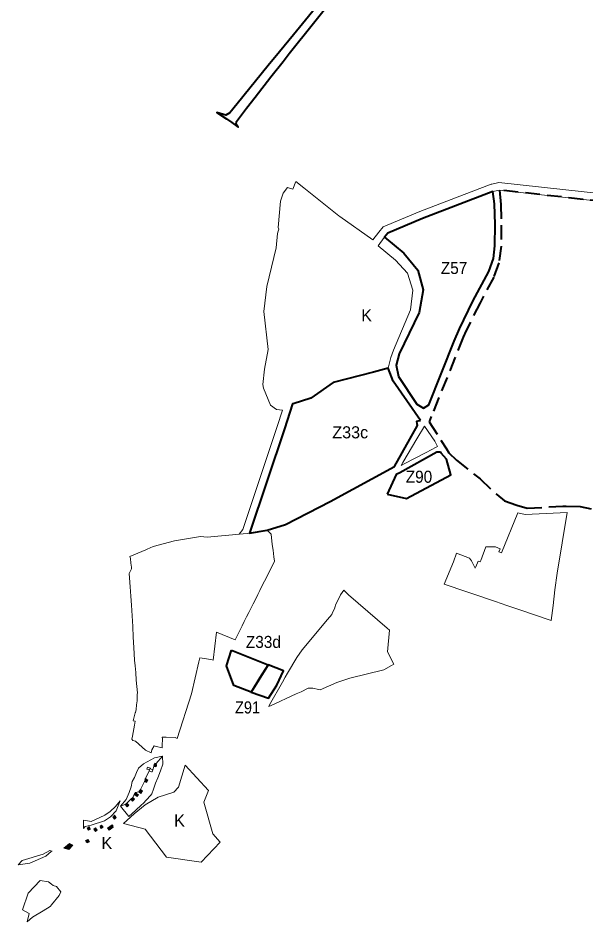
# Model space of a CAD drawing. Extents: x -650276 to -642489, y -1074425 to -1066658.
# Drawn here: x -648979 to -647851, y -1074425 to -1072629 of the extents above; entities that cross this region are included whole.
import ezdxf

# ---------------------------------------------------------------- set-up
doc = ezdxf.new("R2010")
doc.units = 0
doc.header["$LTSCALE"] = 9.6
doc.linetypes.add('MEDIUM_DASHED', pattern=[4.5, 3, -1.5])
for name, color, linetype, lineweight in [('1', 7, 'Continuous', 13), ('43', 7, 'Continuous', 13), ('44', 7, 'Continuous', 40), ('45', 7, 'Continuous', 40), ('46', 7, 'Continuous', 13), ('47', 7, 'Continuous', 13), ('61', 7, 'MEDIUM_DASHED', 40)]:
    doc.layers.add(name, color=color, linetype=linetype, lineweight=lineweight)

msp = doc.modelspace()

# ---------------------------------------------------------------- hatches: boundary and pattern name
at = {"layer": '1'}
for points in [[(-648706.9, -1074109.25), (-648704.01, -1074109.75), (-648704.38, -1074112.26), (-648703.29, -1074112.42), (-648703.74, -1074115.5), (-648704.71, -1074115.36), (-648704.9, -1074116.65), (-648708.61, -1074116.05), (-648707.91, -1074111.29), (-648707.22, -1074111.39)], [(-648727.44, -1074145.52), (-648725.66, -1074142.45), (-648726.64, -1074141.85), (-648725.61, -1074140.1), (-648723.09, -1074141.53), (-648720.64, -1074142.98), (-648723.51, -1074147.87)], [(-648731.11, -1074164.51), (-648734.73, -1074169.43), (-648738.83, -1074166.37), (-648735.22, -1074161.48)], [(-648751.18, -1074184.57), (-648747.5, -1074181.2), (-648750.88, -1074177.44), (-648754.61, -1074180.84)], [(-648739.31, -1074171.85), (-648742.22, -1074175.9), (-648748.17, -1074171.66), (-648745.37, -1074167.73), (-648743.97, -1074168.73), (-648743.97, -1074168.73)], [(-648761.71, -1074196.08), (-648758.47, -1074193.06), (-648762.43, -1074188.71), (-648765.67, -1074191.74)], [(-648787.14, -1074220.53), (-648783.43, -1074217.6), (-648784.21, -1074216.62), (-648787.24, -1074212.83), (-648788.26, -1074213.64), (-648787.58, -1074214.5), (-648790.3, -1074216.64)], [(-648834.62, -1074240.17), (-648835.22, -1074239.19), (-648837.67, -1074235.14), (-648838.8, -1074235.82), (-648838.27, -1074236.69), (-648841.13, -1074238.42), (-648838.64, -1074242.6)], [(-648821.27, -1074242.64), (-648824.7, -1074245.22), (-648828.21, -1074240.31), (-648824.82, -1074237.88)], [(-648813.64, -1074239.44), (-648809.8, -1074236.74), (-648812.71, -1074232.64), (-648815.51, -1074234.63), (-648814.75, -1074235.7), (-648815.76, -1074236.42)], [(-648800.8, -1074238.18), (-648791.75, -1074231.61), (-648789.51, -1074234.71), (-648790.46, -1074235.4), (-648789.81, -1074236.29), (-648797.83, -1074242.19)], [(-648844.44, -1074262.8), (-648839.91, -1074260.94), (-648839.51, -1074261.94), (-648838.46, -1074261.5), (-648836.72, -1074265.79), (-648841.46, -1074267.7), (-648842.1, -1074266.12), (-648842.92, -1074266.45), (-648843.1, -1074266.03), (-648843.33, -1074266.13), (-648843.55, -1074265.61), (-648843.31, -1074265.51)]]:
    msp.add_hatch(color=256, dxfattribs=at).paths.add_polyline_path(points)
at = {"layer": '47'}
msp.add_hatch(color=256, dxfattribs=at).paths.add_polyline_path([(-648876.21, -1074268.73), (-648887.619, -1074278.134), (-648877.799, -1074280.64), (-648870.041, -1074271.932)])

# ---------------------------------------------------------------- linework, layer by layer
at = {"layer": '1'}
for p, q in [((-648704.01, -1074109.75), (-648691.9, -1074095.66)), ((-648725.61, -1074140.1), (-648718.18, -1074124.67)), ((-648710.78, -1074122.56), (-648708.61, -1074116.05)), ((-648735.22, -1074161.48), (-648727.44, -1074145.52)), ((-648745.37, -1074167.73), (-648738.83, -1074166.37)), ((-648762.43, -1074188.71), (-648754.61, -1074180.84)), ((-648750.88, -1074177.44), (-648748.17, -1074171.66)), ((-648775.1, -1074194.97), (-648765.67, -1074191.74))]:
    msp.add_line(p, q, dxfattribs=at)
for points in [[(-648167.68, -1073492.02), (-648148.27, -1073481.86), (-648145.31, -1073480.31), (-648150.85, -1073469.67), (-648171.18, -1073440.16), (-648186.19, -1073465.35), (-648214.31, -1073512.51), (-648217.71, -1073518.22)], [(-648217.71, -1073518.22), (-648211.86, -1073515.16), (-648167.68, -1073492.02)], [(-647915.79, -1073796.07), (-647911.96, -1073765.02), (-647907.9, -1073732.08), (-647887.52, -1073611.77), (-647970.95, -1073615.21), (-647986.1, -1073612.18), (-648018, -1073691.73), (-648023.29, -1073689.72), (-648020.84, -1073683.33), (-648030.35, -1073679.74), (-648049.05, -1073679.67), (-648059.54, -1073706.72), (-648060.55, -1073709.31), (-648064.72, -1073707.89), (-648068.98, -1073719.26), (-648070.53, -1073722.09), (-648077.83, -1073707.36), (-648081.62, -1073702.08), (-648107.38, -1073692.13), (-648113.89, -1073709.39), (-648132.29, -1073753.96), (-648086.94, -1073768.97), (-648074.98, -1073772.93)], [(-648531.31, -1073654.08), (-648602.91, -1073660.32), (-648616.19, -1073659.15), (-648667.8, -1073668), (-648710.31, -1073679.13), (-648721.94, -1073684.11), (-648725.01, -1073685.42), (-648756.81, -1073699.03), (-648755.2, -1073703.08), (-648754.27, -1073711.87), (-648753.44, -1073719.78), (-648753.02, -1073723.7), (-648757.6, -1073732.5), (-648757, -1073741.26), (-648755.76, -1073759.24), (-648754.49, -1073777.63), (-648753.27, -1073795.38), (-648752.06, -1073816.42), (-648750.84, -1073837.88), (-648749.63, -1073859.01), (-648748.83, -1073879.38), (-648748.15, -1073892.33), (-648747.8, -1073896.44), (-648747.45, -1073900.56), (-648747.09, -1073904.68), (-648746.08, -1073916.36), (-648744.97, -1073929.3), (-648743.69, -1073944.2), (-648741.63, -1073969.96)], [(-648741.63, -1073969.96), (-648741.7, -1073972.86), (-648741.82, -1073977.79), (-648742, -1073985.49), (-648743.07, -1073993.69), (-648744.151, -1074002.577), (-648745.609, -1074008.621), (-648745.79, -1074009.12), (-648750.04, -1074025), (-648746.05, -1074026.17), (-648747.5, -1074033.74), (-648748.85, -1074041.09), (-648750.22, -1074048.45), (-648751.57, -1074055.82), (-648752.57, -1074061.85), (-648750.31, -1074064.07), (-648745.35, -1074065.36), (-648725.36, -1074083.48), (-648714.48, -1074088.54), (-648712.7, -1074083.01), (-648708.17, -1074075), (-648706.15, -1074075.52), (-648703.8, -1074076.13), (-648692.12, -1074079.16), (-648692.04, -1074071.48), (-648691.95, -1074063.59), (-648691.93, -1074061.16), (-648692.17, -1074057.75), (-648684.45, -1074057.86), (-648666.67, -1074058.64), (-648662.25, -1074060.63), (-648634.22, -1073971.89), (-648619.68, -1073908.23), (-648617.72, -1073900.06), (-648595.78, -1073903.41), (-648591.015, -1073904.525), (-648584.31, -1073849.37), (-648547.45, -1073864.3), (-648538.19, -1073845.84), (-648533.57, -1073836.64), (-648529.29, -1073828.1), (-648524.62, -1073818.8), (-648520.19, -1073809.96), (-648515.65, -1073800.92), (-648511.53, -1073792.7), (-648507.19, -1073784.05), (-648502.33, -1073774.36), (-648498.26, -1073766.24), (-648493.51, -1073756.79), (-648489.2, -1073748.19), (-648475.3, -1073720.49), (-648469.41, -1073707.95), (-648470.23, -1073699.85), (-648471.6, -1073686.38), (-648473.61, -1073674.84), (-648475.51, -1073654.52), (-648483.58, -1073646.7), (-648514.23, -1073652.37), (-648522.79, -1073653.23), (-648531.31, -1073654.08)], [(-648477.31, -1073995.35), (-648425.92, -1073971.61), (-648416.09, -1073967.48), (-648402.35, -1073960.34), (-648393.32, -1073960.33), (-648381.56, -1073963.36), (-648378.47, -1073963.46), (-648345.65, -1073948.97), (-648319.3, -1073940.41), (-648251.71, -1073923.92), (-648236.64, -1073915.49), (-648232.32, -1073912.96), (-648244.96, -1073888.56), (-648240.9, -1073844.99), (-648245.45, -1073841.08), (-648322.08, -1073775.04), (-648331.74, -1073765.85), (-648337.91, -1073774.87), (-648340.74, -1073780.66), (-648347.38, -1073793.82)], [(-648074.98, -1073772.93), (-648030.44, -1073788.51), (-648007.95, -1073796.14), (-647983.68, -1073804.37), (-647919.33, -1073826.21), (-647915.79, -1073796.07)], [(-648347.38, -1073793.82), (-648349.12, -1073800.06), (-648349.58, -1073801.08), (-648354.57, -1073812.08), (-648355.37, -1073813.85), (-648363.65, -1073823.85), (-648413.91, -1073884.54), (-648424.51, -1073899.37), (-648443.35, -1073930.53), (-648447.77, -1073938.64), (-648453.11, -1073948.16), (-648478.94, -1073993.79), (-648480.31, -1073996.63), (-648477.31, -1073995.35)], [(-648775.1, -1074194.97), (-648758.41, -1074215.05), (-648745.22, -1074203.28), (-648733.69, -1074192.38), (-648730.34, -1074189.22), (-648723.64, -1074182.09), (-648715.37, -1074173.28), (-648712.77, -1074170.51), (-648709.34, -1074161.26), (-648705.61, -1074149.4), (-648700.77, -1074138.18), (-648695.83, -1074124.88), (-648690.92, -1074111.64), (-648691.9, -1074095.66), (-648704.01, -1074109.75)], [(-648691.9, -1074095.66), (-648707.44, -1074098.79), (-648729.24, -1074110.84), (-648739.31, -1074119.01), (-648743.55, -1074127.69), (-648747.25, -1074137.56), (-648751.97, -1074146.03), (-648753.74, -1074156.28), (-648758.05, -1074167.41)], [(-648704.01, -1074109.75), (-648704.38, -1074112.26), (-648703.29, -1074112.42), (-648703.74, -1074115.5), (-648704.71, -1074115.36), (-648704.9, -1074116.65), (-648708.61, -1074116.05), (-648710.78, -1074122.56), (-648712.32, -1074126.72), (-648713.61, -1074126.32), (-648718.18, -1074124.67), (-648725.61, -1074140.1)], [(-648708.61, -1074116.05), (-648707.91, -1074111.29), (-648707.22, -1074111.39), (-648706.9, -1074109.25), (-648704.01, -1074109.75), (-648691.9, -1074095.66)], [(-648727.44, -1074145.52), (-648725.66, -1074142.45), (-648726.64, -1074141.85), (-648725.61, -1074140.1), (-648718.18, -1074124.67), (-648717.56, -1074122.89), (-648722.84, -1074120.98)], [(-648722.84, -1074120.98), (-648721.39, -1074116.99), (-648715.22, -1074119.43), (-648715.7, -1074120.74), (-648712.07, -1074122.08), (-648710.78, -1074122.56), (-648708.61, -1074116.05)], [(-648715.7, -1074120.74), (-648715.22, -1074119.43), (-648721.39, -1074116.99), (-648722.84, -1074120.98), (-648717.56, -1074122.89), (-648717.558, -1074122.891)], [(-648717.558, -1074122.891), (-648718.18, -1074124.67), (-648713.61, -1074126.32)], [(-648717.558, -1074122.891), (-648716.68, -1074120.38), (-648715.7, -1074120.741)], [(-648713.61, -1074126.32), (-648712.32, -1074126.72), (-648710.78, -1074122.56), (-648712.07, -1074122.08), (-648716.68, -1074120.38), (-648717.558, -1074122.891)], [(-648758.05, -1074167.41), (-648763.85, -1074181.6), (-648775.1, -1074194.97), (-648765.67, -1074191.74), (-648762.43, -1074188.71), (-648754.61, -1074180.84), (-648750.88, -1074177.44), (-648748.17, -1074171.66), (-648745.37, -1074167.73), (-648738.83, -1074166.37), (-648735.22, -1074161.48), (-648727.44, -1074145.52)], [(-648725.61, -1074140.1), (-648723.09, -1074141.53), (-648720.64, -1074142.98), (-648723.51, -1074147.87), (-648727.44, -1074145.52), (-648735.22, -1074161.48)], [(-648734.73, -1074169.43), (-648738.83, -1074166.37), (-648745.37, -1074167.73)], [(-648735.22, -1074161.48), (-648731.11, -1074164.51), (-648734.73, -1074169.43)], [(-648750.88, -1074177.44), (-648747.5, -1074181.2), (-648751.18, -1074184.57), (-648754.61, -1074180.84), (-648762.43, -1074188.71), (-648758.47, -1074193.06)], [(-648745.37, -1074167.73), (-648743.97, -1074168.73), (-648743.97, -1074168.73), (-648739.31, -1074171.85), (-648742.22, -1074175.9), (-648748.17, -1074171.66), (-648750.88, -1074177.44)], [(-648758.47, -1074193.06), (-648761.71, -1074196.08), (-648765.67, -1074191.74), (-648775.1, -1074194.97)], [(-648934.81, -1074342.16), (-648958.23, -1074367.89), (-648969.59, -1074400.58), (-648956.69, -1074408.11), (-648960.37, -1074424.7)], [(-648960.37, -1074424.7), (-648949.75, -1074415.44), (-648928.85, -1074402.42), (-648914.83, -1074393.86), (-648914.34, -1074393.35), (-648911.88, -1074390.74), (-648896.94, -1074371.93), (-648893.77, -1074365.14), (-648902.52, -1074354.41), (-648908.69, -1074352.43), (-648912.4, -1074349.53), (-648917.94, -1074345.05), (-648934.81, -1074342.16)]]:
    msp.add_lwpolyline(points, dxfattribs=at)
for points in [[(-648706.9, -1074109.25), (-648704.01, -1074109.75), (-648704.38, -1074112.26), (-648703.29, -1074112.42), (-648703.74, -1074115.5), (-648704.71, -1074115.36), (-648704.9, -1074116.65), (-648708.61, -1074116.05), (-648707.91, -1074111.29), (-648707.22, -1074111.39)], [(-648727.44, -1074145.52), (-648725.66, -1074142.45), (-648726.64, -1074141.85), (-648725.61, -1074140.1), (-648723.09, -1074141.53), (-648720.64, -1074142.98), (-648723.51, -1074147.87)], [(-648731.11, -1074164.51), (-648734.73, -1074169.43), (-648738.83, -1074166.37), (-648735.22, -1074161.48)], [(-648751.18, -1074184.57), (-648747.5, -1074181.2), (-648750.88, -1074177.44), (-648754.61, -1074180.84)], [(-648739.31, -1074171.85), (-648742.22, -1074175.9), (-648748.17, -1074171.66), (-648745.37, -1074167.73), (-648743.97, -1074168.73), (-648743.97, -1074168.73)], [(-648761.71, -1074196.08), (-648758.47, -1074193.06), (-648762.43, -1074188.71), (-648765.67, -1074191.74)], [(-648787.14, -1074220.53), (-648783.43, -1074217.6), (-648784.21, -1074216.62), (-648787.24, -1074212.83), (-648788.26, -1074213.64), (-648787.58, -1074214.5), (-648790.3, -1074216.64)], [(-648834.62, -1074240.17), (-648835.22, -1074239.19), (-648837.67, -1074235.14), (-648838.8, -1074235.82), (-648838.27, -1074236.69), (-648841.13, -1074238.42), (-648838.64, -1074242.6)], [(-648821.27, -1074242.64), (-648824.7, -1074245.22), (-648828.21, -1074240.31), (-648824.82, -1074237.88)], [(-648813.64, -1074239.44), (-648809.8, -1074236.74), (-648812.71, -1074232.64), (-648815.51, -1074234.63), (-648814.75, -1074235.7), (-648815.76, -1074236.42)], [(-648800.8, -1074238.18), (-648791.75, -1074231.61), (-648789.51, -1074234.71), (-648790.46, -1074235.4), (-648789.81, -1074236.29), (-648797.83, -1074242.19)], [(-648844.44, -1074262.8), (-648839.91, -1074260.94), (-648839.51, -1074261.94), (-648838.46, -1074261.5), (-648836.72, -1074265.79), (-648841.46, -1074267.7), (-648842.1, -1074266.12), (-648842.92, -1074266.45), (-648843.1, -1074266.03), (-648843.33, -1074266.13), (-648843.55, -1074265.61), (-648843.31, -1074265.51)]]:
    msp.add_lwpolyline(points, close=True, dxfattribs=at)
at = {"layer": '44'}
msp.add_line((-648245.341, -1073575.152), (-648207, -1073584), dxfattribs=at)
for points in [[(-648369.37, -1072585.645), (-648431.557, -1072662.77), (-648459.243, -1072696.417), (-648481.468, -1072723.736), (-648543.255, -1072800.016), (-648557.588, -1072817.727), (-648565.726, -1072822.048), (-648583.407, -1072817.256), (-648564.86, -1072829.45), (-648554.22, -1072836.89), (-648541.102, -1072846.281), (-648545.462, -1072840.329), (-648544.632, -1072835.177), (-648524.979, -1072808.383), (-648507.503, -1072786.605), (-648476.204, -1072746.1), (-648452.274, -1072715.637), (-648439.912, -1072699.826), (-648391.796, -1072639.344), (-648333.178, -1072565.837)], [(-648139.56, -1073491.4), (-648146.4, -1073491.55), (-648220.42, -1073532.43), (-648227.63, -1073535.89), (-648245.341, -1073575.152)], [(-648207, -1073584), (-648119, -1073537), (-648127.31, -1073505.75), (-648138.41, -1073493.62), (-648139.56, -1073491.4)]]:
    msp.add_lwpolyline(points, dxfattribs=at)
msp.add_lwpolyline([(-648515.333, -1073968.584), (-648480.86, -1073980.25), (-648464.44, -1073954.69), (-648451.05, -1073925.87), (-648481.749, -1073913.76), (-648498, -1073940)], close=True, dxfattribs=at)
at = {"layer": '45'}
for points in [[(-648030.86, -1073039.71), (-648032.09, -1072998.65), (-648035.592, -1072974.222), (-648175.061, -1073027.551), (-648244.214, -1073056.657), (-648250.491, -1073064.698), (-648212.22, -1073096.39), (-648184.37, -1073129.89)], [(-648030.86, -1073039.71), (-648032.09, -1072998.65), (-648035.592, -1072974.222), (-648175.061, -1073027.551), (-648244.214, -1073056.657), (-648250.491, -1073064.698), (-648212.22, -1073096.39), (-648184.37, -1073129.89)], [(-648101.67, -1073246.63), (-648075.34, -1073191.93), (-648043.29, -1073132.97), (-648034.43, -1073107.07), (-648031.8, -1073082.07), (-648030.86, -1073039.71)], [(-648101.67, -1073246.63), (-648075.34, -1073191.93), (-648043.29, -1073132.97), (-648034.43, -1073107.07), (-648031.8, -1073082.07), (-648030.86, -1073039.71)], [(-648184.37, -1073129.89), (-648174.03, -1073168.94), (-648182.12, -1073214.56), (-648221.39, -1073296.24), (-648227.75, -1073318.75), (-648223.03, -1073341.59), (-648186.47, -1073396.47), (-648173.38, -1073404.03)], [(-648184.37, -1073129.89), (-648174.03, -1073168.94), (-648182.12, -1073214.56), (-648221.39, -1073296.24), (-648227.75, -1073318.75), (-648223.03, -1073341.59), (-648186.47, -1073396.47), (-648173.38, -1073404.03)], [(-648173.38, -1073404.03), (-648162.55, -1073397.4), (-648112.36, -1073270.87), (-648101.67, -1073246.63)], [(-648173.38, -1073404.03), (-648162.55, -1073397.4), (-648112.36, -1073270.87), (-648101.67, -1073246.63)], [(-648272.642, -1073332.558), (-648352.312, -1073353), (-648397.062, -1073384.375)], [(-648272.642, -1073332.558), (-648352.312, -1073353), (-648397.062, -1073384.375)], [(-648179.07, -1073428.81), (-648233.36, -1073350.68), (-648243.08, -1073325.04), (-648272.642, -1073332.558)], [(-648179.07, -1073428.81), (-648233.36, -1073350.68), (-648243.08, -1073325.04), (-648272.642, -1073332.558)], [(-648397.062, -1073384.375), (-648432.187, -1073395.625), (-648433.206, -1073395.51), (-648449.599, -1073445.278)], [(-648397.062, -1073384.375), (-648432.187, -1073395.625), (-648433.206, -1073395.51), (-648449.599, -1073445.278)], [(-648447.06, -1073635.39), (-648358.69, -1073589.35), (-648230.81, -1073520.18), (-648185.34, -1073438.91), (-648185.82, -1073435.12), (-648186.46, -1073430.01), (-648183.46, -1073429.52), (-648179.07, -1073428.81)], [(-648447.06, -1073635.39), (-648358.69, -1073589.35), (-648230.81, -1073520.18), (-648185.34, -1073438.91), (-648185.82, -1073435.12), (-648186.46, -1073430.01), (-648183.46, -1073429.52), (-648179.07, -1073428.81)], [(-648449.599, -1073445.278), (-648518.867, -1073652.836), (-648483.58, -1073646.7), (-648447.06, -1073635.39), (-648447.06, -1073635.39)], [(-648449.599, -1073445.278), (-648518.867, -1073652.836), (-648483.58, -1073646.7), (-648447.06, -1073635.39), (-648447.06, -1073635.39)]]:
    msp.add_lwpolyline(points, dxfattribs=at)
msp.add_lwpolyline([(-648554.42, -1073885.092), (-648481.749, -1073913.76), (-648515.333, -1073968.584), (-648549.76, -1073954.86), (-648564.75, -1073915.91)], close=True, dxfattribs=at)
at = {"layer": '47'}
for points in [[(-648426.547, -1072954.108), (-648432.527, -1072969.463), (-648443.591, -1072965.983), (-648451.657, -1072977.25), (-648456.2, -1072989.149), (-648457.123, -1072993.118), (-648461.979, -1073045.585), (-648460.355, -1073048.753), (-648461.973, -1073052.688), (-648463.036, -1073057.011), (-648465.708, -1073085.876), (-648484.661, -1073162.812), (-648490.539, -1073212.35), (-648481.853, -1073287.675), (-648489.355, -1073326.567), (-648492.485, -1073357.358), (-648491.34, -1073364.805), (-648477.028, -1073398.055), (-648464.929, -1073407.031), (-648453.228, -1073408.349), (-648463.838, -1073440.559), (-648513.627, -1073589.927), (-648532.252, -1073645.567), (-648539.599, -1073654.802), (-648531.31, -1073654.08), (-648522.79, -1073653.23), (-648518.867, -1073652.836), (-648499.399, -1073594.679), (-648449.599, -1073445.278), (-648433.206, -1073395.51), (-648432.187, -1073395.625), (-648397.062, -1073384.375), (-648378.125, -1073370.875), (-648352.312, -1073353), (-648314.687, -1073343.25), (-648272.642, -1073332.558), (-648243.08, -1073325.04), (-648237.98, -1073303.4), (-648232.64, -1073289.31), (-648198.7, -1073209.08), (-648194.2, -1073170.13), (-648205.04, -1073136.07), (-648228.91, -1073110.54), (-648262.917, -1073081.543), (-648251.027, -1073065.418), (-648250.491, -1073064.698), (-648244.214, -1073056.657), (-648175.061, -1073027.551), (-648035.592, -1072974.222), (-648022.279, -1072971.102), (-647813.331, -1072994.317)], [(-647811.752, -1072979.4), (-648023.495, -1072955.875), (-648023.498, -1072955.876), (-648023.818, -1072955.949), (-648037.595, -1072959.123), (-648038.877, -1072959.418), (-648180.651, -1073013.629), (-648253.635, -1073044.348), (-648261.902, -1073054.939), (-648273.756, -1073070.132), (-648273.756, -1073070.132), (-648339.58, -1073023.82), (-648341.495, -1073022.285), (-648411.09, -1072966.5), (-648426.547, -1072954.108)], [(-648833.449, -1074232.685), (-648807.065, -1074223.704), (-648794.902, -1074216.219), (-648783.863, -1074204.056), (-648775.93, -1074183.91), (-648784.8, -1074195.26), (-648795.65, -1074205.35), (-648806.55, -1074212.62), (-648833.11, -1074225.2), (-648844.05, -1074223.24), (-648848.28, -1074222.49), (-648848.696, -1074238.993)], [(-648848.696, -1074238.993), (-648845.424, -1074235.305), (-648833.449, -1074232.685)]]:
    msp.add_lwpolyline(points, dxfattribs=at)
for points in [[(-648725.93, -1074240.58), (-648683.5, -1074296.12), (-648683.5, -1074296.12), (-648614.6, -1074306.17), (-648577.25, -1074266.06), (-648591.67, -1074249.72), (-648609.49, -1074186.61), (-648600.53, -1074163.47), (-648646.42, -1074113.19), (-648660.16, -1074156.75), (-648669.01, -1074167.27), (-648700.45, -1074176.73), (-648726.23, -1074192.02), (-648747.74, -1074210.12), (-648768.94, -1074229.25)], [(-648876.21, -1074268.73), (-648887.619, -1074278.134), (-648877.799, -1074280.64), (-648870.041, -1074271.932)], [(-648978.575, -1074311.426), (-648955.265, -1074308.325), (-648923.698, -1074294.313), (-648912.63, -1074284.912), (-648910.988, -1074284.211), (-648915.73, -1074283.08), (-648929.03, -1074290.14), (-648970.3, -1074302.9)]]:
    msp.add_lwpolyline(points, close=True, dxfattribs=at)
at = {"layer": '61'}
msp.add_lwpolyline([(-647813.331, -1072994.317), (-648022.279, -1072971.102), (-648019.38, -1072999.62), (-648018.59, -1073040.65), (-648019.04, -1073082.7), (-648023.38, -1073115.63), (-648033.71, -1073143.76), (-648060.75, -1073194.72), (-648088.41, -1073249.9), (-648094.092, -1073263.034), (-648157.74, -1073420.89), (-648161.7, -1073431.46), (-648127.64, -1073484.76), (-648122.58, -1073492.69), (-648107.53, -1073507.68), (-648060.92, -1073544.52), (-648027.7, -1073575.75), (-648012.55, -1073588.03), (-647987.9, -1073597.16), (-647967.15, -1073602.95), (-647896.59, -1073598.78), (-647889.64, -1073598.65), (-647861.92, -1073599.87), (-647840.12, -1073604.27)], dxfattribs=at)

# ---------------------------------------------------------------- texts
at = {"layer": '43'}
for p in [(-648296.955, -1073231.892), (-648668.641, -1074235.329), (-648812.985, -1074279.86)]:
    msp.add_text('K', height=24, dxfattribs=at).set_placement(p)
at = {"layer": '44'}
for s, width, p in [('Z90', 0.95, (-648208.451, -1073552.422)), ('Z90', 0.95, (-648208.451, -1073552.422)), ('Z91', 0.9, (-648547.629, -1074010.653))]:
    msp.add_text(s, height=24, dxfattribs=dict(at, width=width)).set_placement(p)
at = {"layer": '46', "width": 0.95}
for s, p in [('Z57', (-648138.747, -1073137.744)), ('Z57', (-648138.747, -1073137.744)), ('Z33d', (-648525.981, -1073880.565))]:
    msp.add_text(s, height=24, dxfattribs=at).set_placement(p)
at = {"layer": '46'}
msp.add_text('Z33c', height=24, dxfattribs=at).set_placement((-648354.418, -1073464.218))
msp.add_text('Z33c', height=24, dxfattribs=at).set_placement((-648354.418, -1073464.218))

doc.saveas('drawing.dxf')
